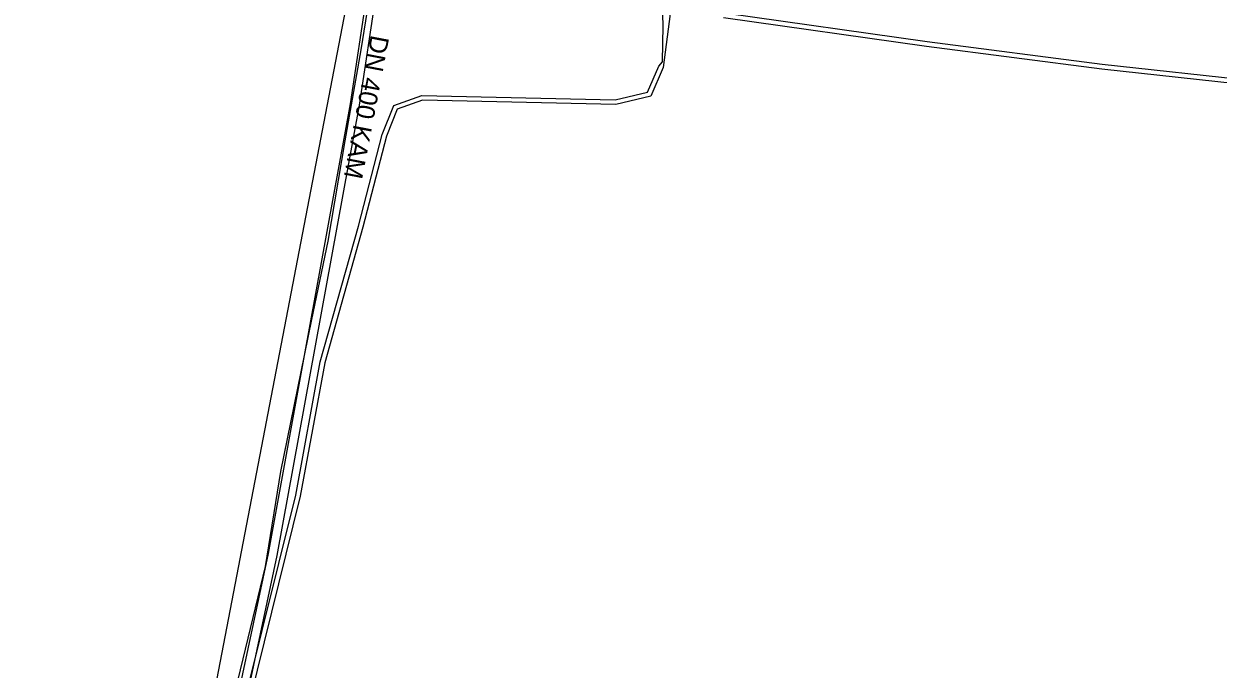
# Model space of a CAD drawing. Extents: x -598233 to -596890, y -1157848 to -1156431.
# Drawn here: x -598008.8 to -597957.3, y -1156873 to -1156845.2 of the extents above; entities that cross this region are included whole.
import ezdxf

# ---------------------------------------------------------------- set-up
doc = ezdxf.new("R2010")
doc.units = 0
for name, color, linetype in [('Vrstva 42', 7, 'Continuous'), ('Vrstva 44', 7, 'Continuous'), ('Vrstva 5', 7, 'Continuous'), ('Vrstva 8', 7, 'Continuous')]:
    doc.layers.add(name, color=color, linetype=linetype)

msp = doc.modelspace()

# ---------------------------------------------------------------- linework, layer by layer
at = {"layer": 'Vrstva 42'}
for points in [[(-598003.78, -1156895.63), (-598002.867, -1156893.497), (-598002.413, -1156890.792), (-598001.763, -1156886.546), (-597997.844, -1156868.129), (-597994.303, -1156848.743), (-597993.572, -1156843.878), (-597993.285, -1156841.737), (-597993.225, -1156841.282), (-597993.198, -1156841.081), (-597993.196, -1156841.069), (-597993.345, -1156841.061), (-597993.558, -1156841.051), (-597998.094, -1156840.819), (-598000.335, -1156840.151), (-598006.393, -1156840.402), (-598007.297, -1156840.053), (-598007.758, -1156841.612), (-598008.29, -1156841.689)], [(-598008.255, -1156842.088), (-598007.447, -1156841.971), (-598007.036, -1156840.582), (-598006.46, -1156840.805), (-598000.385, -1156840.554), (-597998.162, -1156841.216), (-597993.65, -1156841.446), (-597993.968, -1156843.822), (-597994.697, -1156848.677), (-597996.678, -1156859.523), (-597998.236, -1156868.051), (-598001.271, -1156882.312)], [(-597982.178, -1156840.3), (-597983.263, -1156840.325), (-597983.321, -1156840.327), (-597983.383, -1156840.328), (-597983.386, -1156840.338), (-597983.414, -1156840.445), (-597983.426, -1156840.488), (-597983.443, -1156840.551), (-597983.45, -1156840.579), (-597983.501, -1156840.77), (-597983.579, -1156841.061), (-597983.472, -1156843.158), (-597982.756, -1156843.701), (-597982.537, -1156843.867), (-597981.74, -1156844.041), (-597981.207, -1156844.156), (-597980.768, -1156844.252), (-597978.592, -1156844.762), (-597969.857, -1156846.001), (-597962.318, -1156846.971), (-597955.74, -1156847.69)], [(-597993.58, -1156842.24), (-597994.24, -1156846.36), (-597994.93, -1156850.27), (-597995.66, -1156854.6), (-597996.36, -1156857.97), (-597996.678, -1156859.523), (-597997.7, -1156864.51), (-597998.36, -1156868.61), (-598000.19, -1156876.14)], [(-597978.628, -1156844.958), (-597969.883, -1156846.199), (-597962.342, -1156847.169), (-597955.76, -1156847.89)]]:
    msp.add_lwpolyline(points, dxfattribs=at)
at = {"layer": 'Vrstva 44'}
for points in [[(-597981.23, -1156845.31), (-597981.26, -1156844.43), (-597981.67, -1156844.08), (-597983.011, -1156843.41), (-597983.63, -1156843.309), (-597989.53, -1156842.723), (-597990.128, -1156842.23), (-597990.829, -1156840.369), (-597990.91, -1156837.621), (-597990.73, -1156828.166), (-597990.56, -1156819.109), (-597990.66, -1156809.698), (-597990.628, -1156808.753), (-597990.889, -1156805.169), (-597991.556, -1156802.999)], [(-597979.593, -1156842.627), (-597980.874, -1156844.477), (-597981.223, -1156847.117), (-597981.758, -1156848.346), (-597983.269, -1156848.71), (-597991.584, -1156848.53), (-597992.674, -1156848.909), (-597993.135, -1156850.071), (-597994.153, -1156853.996), (-597995.792, -1156859.833), (-597996.852, -1156865.581), (-597999.023, -1156874.344)], [(-598008.75, -1156927.27), (-598008.471, -1156926.256), (-598008.18, -1156923.13), (-598006.998, -1156913.143), (-598005.373, -1156906.096), (-598003.093, -1156903.246), (-598002.618, -1156900.971), (-598002.031, -1156897.643), (-598002.19, -1156893.405), (-598000.919, -1156884.266), (-597999.838, -1156876.74), (-597999.217, -1156874.295), (-597997.048, -1156865.539), (-597995.987, -1156859.788), (-597994.346, -1156853.944), (-597993.326, -1156850.009), (-597992.826, -1156848.75), (-597991.616, -1156848.329), (-597983.291, -1156848.509), (-597981.902, -1156848.175), (-597981.418, -1156847.063), (-597981.26, -1156846.87), (-597981.23, -1156845.31)]]:
    msp.add_lwpolyline(points, dxfattribs=at)
at = {"layer": 'Vrstva 5'}
msp.add_line((-597994.85, -1156844.31), (-598000.95, -1156876.07), dxfattribs=at)

# ---------------------------------------------------------------- texts
at = {"layer": 'Vrstva 8'}
msp.add_text('DN 400 KAM', height=0.8, rotation=259.1488, dxfattribs=at).set_placement((-597993.804, -1156845.686))

doc.saveas('drawing.dxf')
